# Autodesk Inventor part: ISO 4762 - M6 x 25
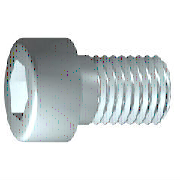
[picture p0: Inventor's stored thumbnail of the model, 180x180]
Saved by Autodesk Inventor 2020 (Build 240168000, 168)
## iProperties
Manager: www.cadconsulting.pl
Company: Fabian Stasiak CAD Consulting
Created: 2015-02
Part Number: ISO 4762 - M6 x 25
Material: Stal nierdzewna 440C
Description: Śruba z łbem o zmniejszonych z gniazdem sześciokątnym
Document SubType Name: Modeling
Standard: ISO 4762
Designer: F.Stasiak
Standard Revision: Fourth edition 2004-03-01
Standards Organization: ISO
Language: pl-PL
Size Designation: M6 x 25
Categories: <MemberInstance><Categories><Category DisplayName="Mocowania" InternalName="e4da775c-781d-43d5-af7c-5136215cf5a6" Mnemonic="FSTN"><Category DisplayName="Śruby"
Density: 7.75 g/cm^3
Appearance: Częściowo polerowana
IsCustomPart: 0
Author: F.Stasiak
Subject: Zbiór ćwiczeń. Autodesk Inventor 2020. Kurs podstawowy
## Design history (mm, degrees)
sketch "Szkic1"
  geometry: L1 (-1.333, 0)-(25, 0); L2 (25, 0)-(25, 3); L3 (25, 3)-(2.5, 3); L4 (2.5, 3)-(1.886, 3); L5 (1.886, 3)-(0, 3); L6 (0, 3)-(0, 5); L7 (0, 5)-(-6, 5); L8 (-6, 5)-(-6, 2.887); L9 (-6, 2.887)-(-3, 2.887); L10 (-3, 2.887)-(-1.333, 0); L11 (-12.2, 0)-(31.2, 0) reference; L12 (0, -1)-(0, 6) reference; L13 (2.5, 3)-(0, 3)
  constraints: 22 end point, 6 parallel, 2 collinear, 2 perpendicular, 1 horizontal, 1 point on line
  dimensions: "d1" = 22.5 distance from line of L3.end L2 (= GEL); "d2" = 0.61355 distance of L4.end L3.end (computed from GAL); "d3" = 6 distance between parallel lines of L8 L6 (= KOH); "d4" = 3 distance of L8.end L9.end (= INTI); "d5" = 60 deg angle of L10 L1; "d6" = 6 diameter of L3 L1 (= GD); "d7" = 6 diameter of L5 L1 (= BDM); "d8" = 5.7735 diameter of L9 L1 (= 1.1547 x SW); "d9" = 10 diameter of L7 L1 (= KOD); "d26" = 25 distance between parallel lines of L12 L2 (= NLG)
revolve "Bryła" sketch "Szkic1" stored, may be unused: angle "d10" = 90 deg
sketch "Szkic2"
  geometry: L1 (0, -7)-(0, 7) reference; L2 (-7, 0)-(7, 0) reference; L3 (2.887, 0)-(1.443, -2.5); L4 (1.443, -2.5)-(-1.443, -2.5); L5 (-1.443, -2.5)-(-2.887, 0); L6 (-2.887, 0)-(-1.443, 2.5); L7 (-1.443, 2.5)-(1.443, 2.5); L8 (1.443, 2.5)-(2.887, 0); 2 further points
  constraints: 12 end point, 1 coincident, 1 horizontal alignment, 1 point on line, 12 other
extrude "Szczelina" join sketch "Szkic2" stored distance "d11" = 10; taper "d12" = 0 deg
workplane "Work Plane1"
fillet "Fillet2" dims "d30" = 0.1 (= R)
body "Solid1"
fillet "Zaokrąglenie1" dims "d17" = 0.6 (= RR)
feature "Gwint" dims "d13" = 22.5 (= GEL), "d14" = 0
chamfer "Faza1" distance "d15" = 0.61345 (= -0.5 x SPD + 0.5 x GD); stored, may be unused: second distance "d16" = 0.61345 (= GUL), angle "d27" = 45 deg
other parameters: "GD" = 6 [user parameter; used in 2 equation terms], "NLG" = 25 [user parameter; used in 1 equation term], "GEL" = 22.5 [user parameter; used in 2 equation terms], "KOD" = 10 [user parameter; used in 1 equation term], "KOH" = 6 [user parameter; used in 1 equation term], "INTI" = 3 [user parameter; used in 1 equation term], "GAL" = 0.61345 (= 0.61345 x PTC) [user parameter; used in 1 equation term], "GUL" = 0.61345 (= 0.61345 x PTC) [user parameter; used in 1 equation term], "BDM" = 6 (= NND) [user parameter; used in 1 equation term], "SW" = 5 [user parameter; used in 2 equation terms], "RR" = 0.6 [user parameter; used in 1 equation term], "SPD" = 4.7731 (= NND - 1.2269 x PTC) [user parameter; used in 1 equation term], "d19" = 0, "d28" = 0, "d29" = 0, "R" = 0.1 [user parameter; used in 1 equation term], "TOA" = 30 deg [user parameter], "GD1" = 4.7731 (= THREADDIA - 1.2269 x PTC) [user parameter], "THREADDIA" = 6 [user parameter; used in 1 equation term], "FAWI" = 45 deg [user parameter], "PTC" = 1 [user parameter; used in 5 equation terms], "NND" = 6 [user parameter; used in 2 equation terms], "E0" = 5.775 (= 1.155 x SW) [user parameter]
